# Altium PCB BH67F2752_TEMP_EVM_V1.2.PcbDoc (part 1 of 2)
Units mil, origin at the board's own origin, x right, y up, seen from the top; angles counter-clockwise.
Board outline 4690.02 x 3082.03 mil, 2 copper layers (Top Layer, Bottom Layer); 69 components, 83 nets, 365 pads, 122 vias.
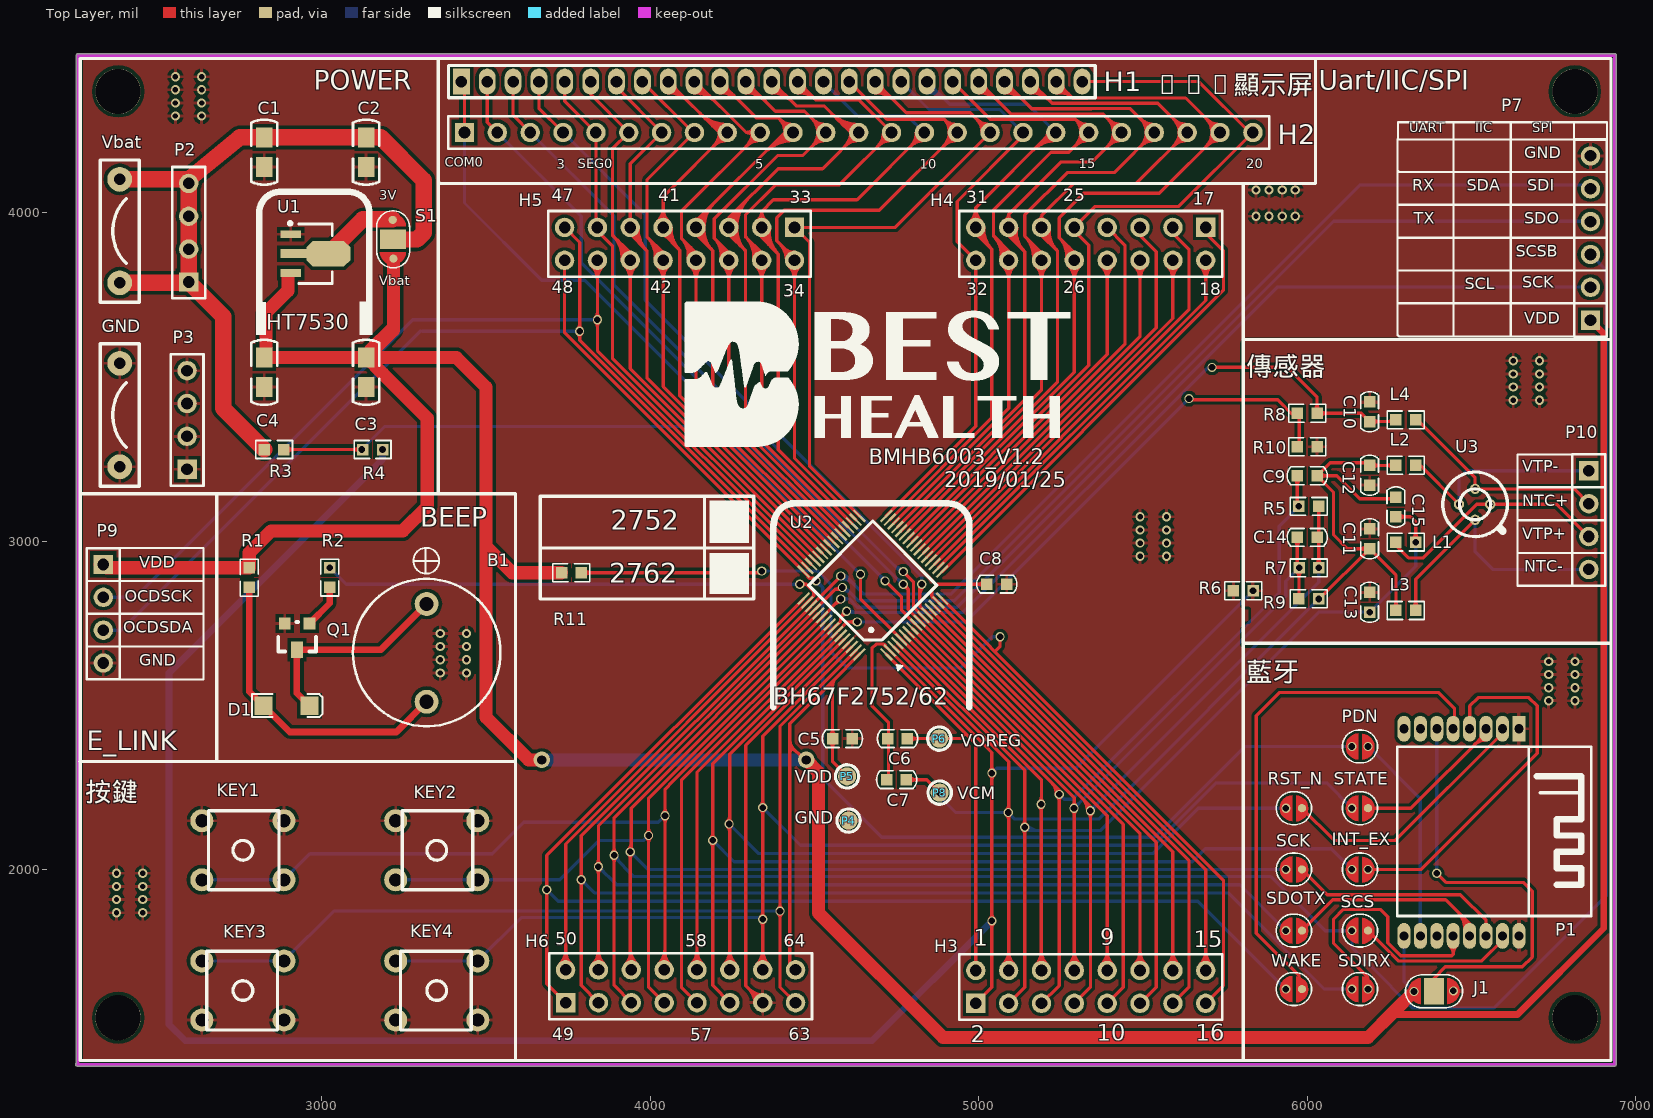
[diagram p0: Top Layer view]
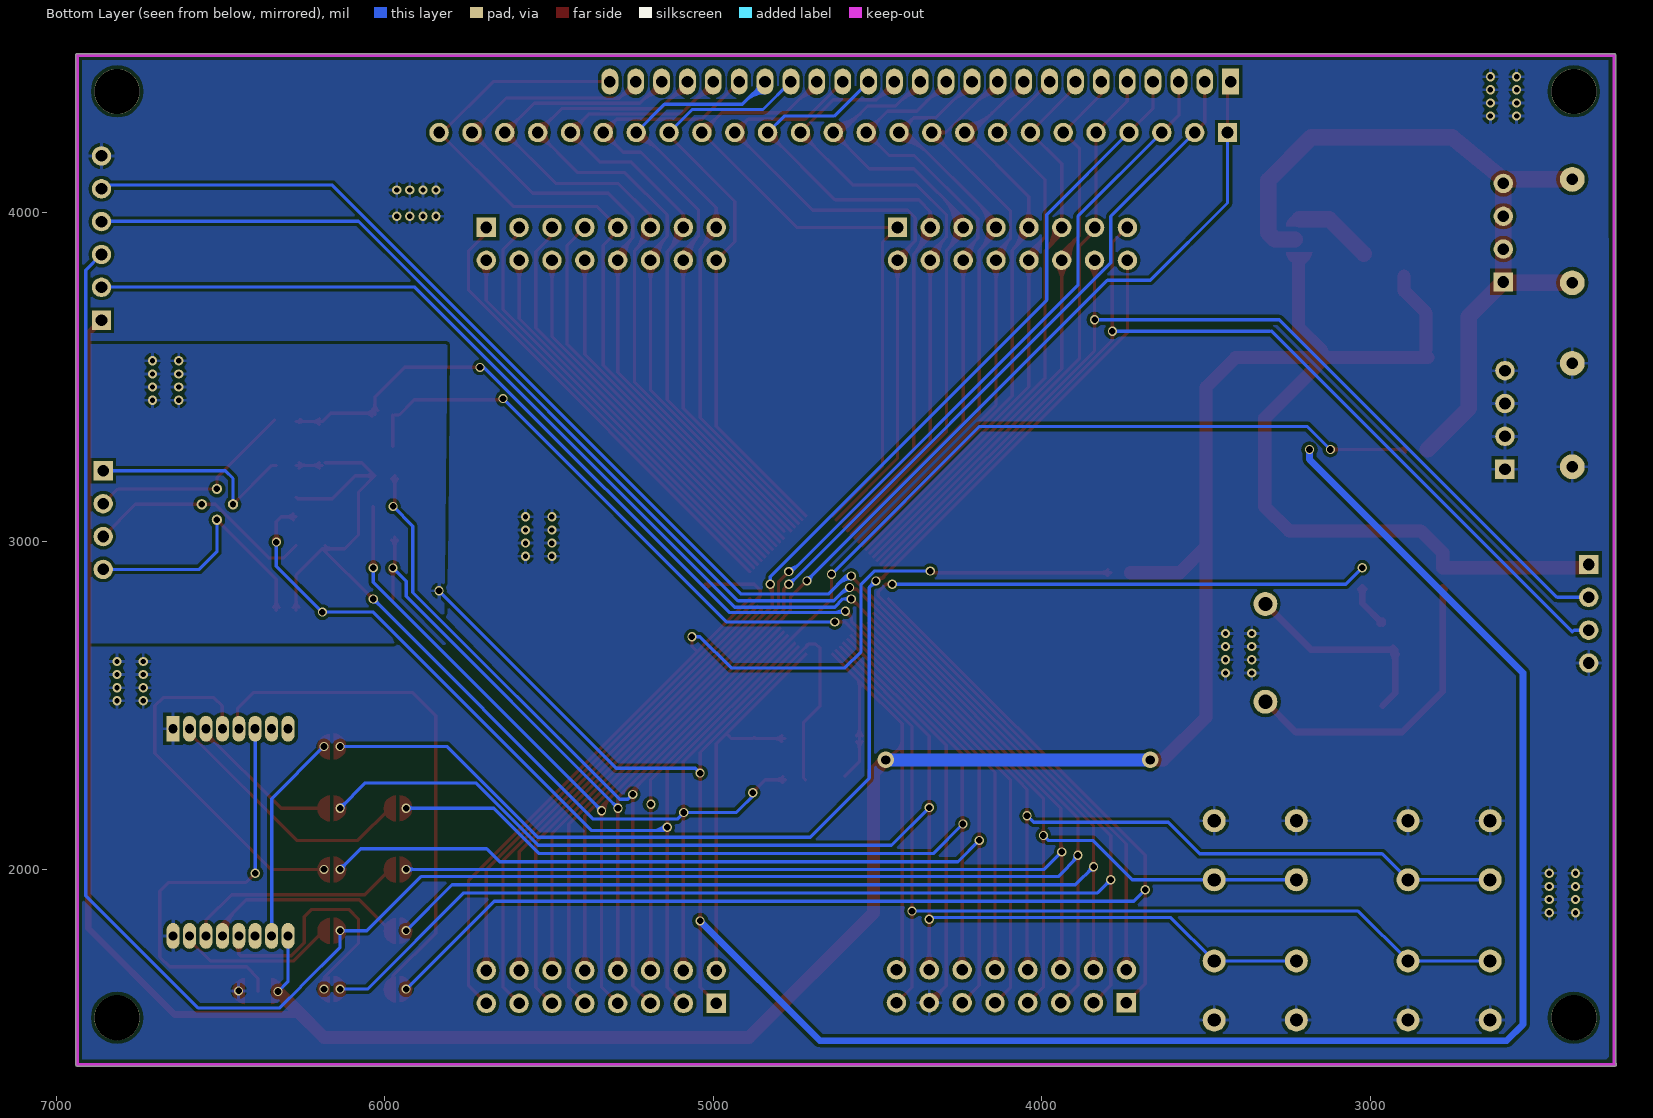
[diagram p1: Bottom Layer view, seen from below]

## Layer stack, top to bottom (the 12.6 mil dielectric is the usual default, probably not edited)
Top Solder: solder mask 0.4, Solder Resist, Dk 3.5
Top Layer: signal copper 1.4
Dielectric1: dielectric 12.6, FR-4, Dk 4.8
Bottom Layer: signal copper 1.4
Bottom Solder: solder mask 0.4, Solder Resist, Dk 3.5

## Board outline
2255.92,1402.93 cw(c2255.92,1407.95) 2252.91,1411.96 2252.91,4479.95 cw(c2257.92,4479.95) 2257.92,4484.97 6935.92,4484.97 cw(c6935.92,4479.95) 6940.94,4479.95 6940.94,1407.95 cw(c6935.92,1407.95) 6935.92,1402.93

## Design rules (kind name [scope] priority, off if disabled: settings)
Clearance Clearance_1 [InPolygon] p1: gap=10
Clearance [All] p2: gap=6
MinimumSolderMaskSliver [All] p1: minsoldermaskwidth=0
NetAntennae [All] p1: netantennaetolerance=1
PolygonConnect [All] p1: connectstyle=Relief reliefconductorwidth=10 reliefentries=4 polygonreliefangle="90 Angle" airgapwidth=10
RoutingVias [All] p1: holewidth=28 width=50 viastyle="Through Hole" minholewidth=10 minwidth=10 maxholewidth=28 maxwidth=50
SilkToSilkClearance [All] p1: silktosilkclearance=0
SilkToSolderMaskClearance [IsPad] p1: minsilkscreentomaskgap=-1 clearancetoexposedcopper=TRUE
SolderMaskExpansion [All] p1: expansion=4
Width [All] p1: maxlimit=50 minlimit=10 preferedwidth=10
26 further rules are at their usual default settings.

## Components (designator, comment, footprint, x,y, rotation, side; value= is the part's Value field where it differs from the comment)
B1 "Beep" BEEP_12MM 3319.29,2810 r270 top
C1 "CAPACITOR" C0805 2825,4140 r90 top
C2 "ECAP" C0805 3135,4230 r270 top
C3 "ECAP" C0805 3135,3560.1 r270 top
C4 "CAPACITOR" C0805 2825,3470 r90 top
C5 "106" CAP_0603 4585,2400 r180 top
C6 "106" CAP_0603 4752.71,2400 r180 top
C7 "105" CAP_0603 4750,2275 r0 top
C8 "104" CAP_0603 5055,2870 r0 top
C9 "104" CAP_0603 6000,3200 r180 top
C10 "104" CAP_0603 6190,3395 r90 top
C11 "104" CAP_0603 6190,3008.24 r90 top
C12 "104" CAP_0603 6190,3201.62 r270 top
C13 "104" CAP_0603 6190,2814.86 r90 top
C14 "104" CAP_0603 6000,3012.73 r180 top
C15 "104" CAP_0603 6270,3105 r270 top
D1 "SS14" DIODE 2962.5,2500 r180 top
GND "CONNET*2" "CLIP POWER PIN" 2385,3385 r90 top (schematic designator GND1)
H1 "HEADER36" "Header25(2mm) - duplicate" 3425,4400 r0 top
H2 "HEADER36" Header252.54mm) 3434.57,4245 r0 top
H3 "HEADER8*2" HEAD2X8 5780,1600 r180 top
H4 "HEADER8*2" 2HEAD2X8 6307,4130 r180 top
H5 "HEADER8*2" 3HEAD2X8 4650.2,3995 r180 top
H6 "HEADER8*2" "4HEAD2X8 - DUPLICATE" 6481.38,1607 r180 top
INT_EX "JUMPER" JUMP_2 6167.05,2000.75 r0 top (schematic designator INT_EX1)
J1 "Header 3" JUMP_3 6435,1550 r180 top
KEY1 "SW-PB" AN66 2760,2060 r90 top
KEY2 "SW-PB" AN66 3350,2060 r90 top
KEY3 "SW-PB" AN66 2760,1633 r270 top
KEY4 "SW-PB" AN66 3350,1633 r270 top
L1 "BEAD" RES_0603 6300,2998.24 r180 top
L2 "BEAD" RES_0603 6300,3231.62 r0 top
L3 "BEAD" RES_0603 6300,2790 r0 top
L4 "BEAD" RES_0603 6300,3370 r0 top
P1 "Header 8X2A" BC7602 6570,2115 r270 top
P2 "Header 4" HDR1X4 2595,3790 r90 top
P3 "Header 4" HDR1X4 2590,3220 r90 top
P4 "PAD" PAD 4485,2200 r0 top
P5 "PAD" PAD 4480.62,2334.49 r0 top
P6 "PAD" PAD 4761.34,2449.49 r0 top
P7 "Header 6H" HEAD1X6 6830,3685 r90 top
P8 "PAD" PAD 4762.48,2285 r0 top
P9 "Header 4" HDR1X4 2335,2930 r270 top
P10 "IRSensor Pin" HDR1X4 6857.36,3215 r270 top
PDN "JUMPER" JUMP_2 6167.05,2374.96 r0 top (schematic designator PDN1)
Q1 "8050" SOT-23 2925,2710 r180 top
R1 "20R" RES_0603 2779.29,2890 r270 top
R2 "1K" RES_0603 3024.29,2890 r90 top
R3 "RES0603" RES_0603 2855,3280 r180 top
R4 "RES0603" RES_0603 3155,3280 r180 top
R5 "RES0603" RES_0603 6004.75,3106.72 r0 top
R6 "RES0603" RES_0603 5805,2850 r0 top
R7 "RES0603" RES_0603 6005.18,2919.45 r180 top
R8 "RES0603" RES_0603 6000,3390 r0 top
R9 "RES0603" RES_0603 6004.75,2825.81 r0 top
R10 "RES0603" RES_0603 6000,3288.54 r180 top
R11 "RES0603" RES_0603 3760,2905 r180 top
RST_N "JUMPER" JUMP_2 5965.97,2187.17 r0 top (schematic designator RST_N1)
S1 "SW-3" JUMP_3 3298.01,3969 r270 top
SCK "JUMPER" JUMP_2 5965.97,2000.75 r0 top (schematic designator SCK1)
SCS "JUMPER" JUMP_2 6167.05,1814.33 r0 top (schematic designator SCS1)
SDIRX "JUMPER" JUMP_2 6167.05,1636.41 r0 top (schematic designator SDIRX1)
SDOTX "JUMPER" JUMP_2 5965.97,1814.33 r0 top (schematic designator SDOTX1)
STATE "JUMPER" JUMP_2 6167.05,2187.17 r0 top (schematic designator STATE1)
U1 "HT7530" SOT89M 2980.63,3876 r0 top
U2 "BH67F2752" 64PIN(LQFP) 4715,2660 r135 top
U3 "IRSensor" TS318_115 6555,3115 r180 top
Vbat "CONNET*2" "CLIP POWER PIN" 2385,3945 r90 top (schematic designator Vbat1)
WAKE "JUMPER" JUMP_2 5965.97,1636.41 r0 top (schematic designator WAKE1)

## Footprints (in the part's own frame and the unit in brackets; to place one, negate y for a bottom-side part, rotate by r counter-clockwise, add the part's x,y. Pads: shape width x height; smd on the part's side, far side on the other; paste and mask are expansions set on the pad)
2HEAD2X8 [mm]
  rect 1.5x1.5 hole 0.9: 1(15.646,4.42)
  round 1.5 hole 0.9: 2(15.646,6.96) 3(18.186,4.42) 4(18.186,6.96) 5(20.726,4.42) 6(20.726,6.96) 7(23.266,4.42) 8(23.266,6.96) 9(25.806,4.42) 10(25.806,6.96) 11(28.346,4.42) 12(28.346,6.96) 13(30.886,4.42) 14(30.886,6.96) 15(33.426,4.42) 16(33.426,6.96)
  silkscreen extent 14.38,3.15 34.7,8.23
3HEAD2X8 [mm]
  rect 1.5x1.5 hole 0.9: 1(5.359,0.991)
  round 1.5 hole 0.9: 2(5.359,3.531) 3(7.899,0.991) 4(7.899,3.531) 5(10.439,0.991) 6(10.439,3.531) 7(12.979,0.991) 8(12.979,3.531) 9(15.519,0.991) 10(15.519,3.531) 11(18.059,0.991) 12(18.059,3.531) 13(20.599,0.991) 14(20.599,3.531) 15(23.139,0.991) 16(23.139,3.531)
  silkscreen extent 4.09,-0.28 24.41,4.8
"4HEAD2X8 - DUPLICATE" [mm]
  rect 1.5x1.5 hole 0.9: 1(69.571,0.279)
  round 1.5 hole 0.9: 2(69.571,-2.261) 3(67.031,0.279) 4(67.031,-2.261) 5(64.491,0.279) 6(64.491,-2.261) 7(61.951,0.279) 8(61.951,-2.261) 9(59.411,0.279) 10(59.411,-2.261) 11(56.871,0.279) 12(56.871,-2.261) 13(54.331,0.279) 14(54.331,-2.261) 15(51.791,0.279) 16(51.791,-2.261)
  silkscreen extent 50.52,-3.53 70.84,1.55
64PIN(LQFP) [mil]
  rect 50x7 smd: 1(-5,0) 2(-5,-16) 3(-5,-32) 4(-5,-48) 5(-5,-64) 6(-5,-80) 7(-5,-96) 8(-5,-112) 9(-5,-128) 10(-5,-144) 11(-5,-160) 12(-5,-176) 13(-5,-192) 14(-5,-208) 15(-5,-224) 16(-5,-240) 33(351,-240) 34(351,-224) 35(351,-208) 36(351,-192) 37(351,-176) 38(351,-160) 39(351,-144) 40(351,-128) 41(351,-112) 42(351,-96) 43(351,-80) 44(351,-64) 45(351,-48) 46(351,-32) 47(351,-16) 48(351,0)
  rect 7x50 smd: 17(53,-298) 18(69,-298) 19(85,-298) 20(101,-298) 21(117,-298) 22(133,-298) 23(149,-298) 24(165,-298) 25(181,-298) 26(197,-298) 27(213,-298) 28(229,-298) 29(245,-298) 30(261,-298) 31(277,-298) 32(293,-298) 49(293,58) 50(277,58) 51(261,58) 52(245,58) 53(229,58) 54(213,58) 55(197,58) 56(181,58) 57(165,58) 58(149,58) 59(133,58) 60(117,58) 61(101,58) 62(85,58) 63(69,58) 64(53,58)
  silkscreen extent -65,-258 311,18
AN66 [mil] "DIP PUSH BOTTON (6MM*6MM)"
  round 70 hole 40: 1(-90,125) 1(-90,-125) 2(90,125) 2(90,-125)
  silkscreen extent -120,-110 120,105
BC7602 [mm]
  rect 2x1 hole 0.7: 1(-8,1.89)
  oval 2x1 hole 0.7: 2(-8,0.62) 3(-8,-0.65) 4(-8,-1.92) 5(-8,-3.19) 6(-8,-4.46) 7(-8,-5.73) 8(-8,-7) 9(8.016,-7) 10(8.016,-5.73) 11(8.016,-4.46) 12(8.016,-3.19) 13(8.016,-1.92) 14(8.016,-0.65) 15(8.016,0.62) 16(8.016,1.89)
  silkscreen extent -6.6,-7.51 6.48,7.48
BEEP_12MM [mm]
  round 1.85 hole 1.1: 1(0,0) 2(7.569,0)
  silkscreen extent -4.34,-5.7 9.46,5.7
C0805 [mil] "0805 CAPCITOR"
  rect 60x50 smd: 1(0,0) 2(90,0)
  silkscreen extent -54,-40 144,40, body extent 6,-25 84,24, height 31
CAP_0603 [mil]
  rect 35x35 smd: 1(-30,0) 2(30,0)
  silkscreen extent -61,-27 61,27
"CLIP POWER PIN" [mm] "USE PAPER CLIP AS POWER PIN(PITCH=8MM)"
  round 1.924 hole 0.9: 1(-4,0) 2(4,0)
  silkscreen extent -5.5,-1.5 5.5,1.5
DIODE [mm]
  rect 1.4x1.4 smd: 1(0,0) 2(3.556,0)
  silkscreen extent -1.02,-0.89 4.44,0.89
HDR1X4 [mm] "Connector; Header; 4 Position"
  rect 1.5x1.5 hole 0.9: 1(0,0)
  round 1.5 hole 0.9: 2(2.54,0) 3(5.08,0) 4(7.62,0)
  silkscreen extent -1.27,-1.27 8.89,1.27
HEAD1X6 [mm]
  rect 1.5x1.5 hole 0.9: 1(-0.287,-0.822)
  round 1.5 hole 0.9: 2(2.253,-0.822) 3(4.793,-0.822) 4(7.333,-0.822) 5(9.873,-0.822) 6(12.413,-0.822)
  silkscreen extent -1.56,-2.09 13.68,0.45
HEAD2X8 [mm]
  round 1.5 hole 0.9: 1(20.041,-2.388) 3(17.501,-2.388) 4(17.501,0.152) 5(14.961,-2.388) 6(14.961,0.152) 7(12.421,-2.388) 8(12.421,0.152) 9(9.881,-2.388) 10(9.881,0.152) 11(7.341,-2.388) 12(7.341,0.152) 13(4.801,-2.388) 14(4.801,0.152) 15(2.261,-2.388) 16(2.261,0.152)
  rect 1.5x1.5 hole 0.9: 2(20.041,0.152)
  silkscreen extent 0.99,-3.66 21.31,1.42
"Header25(2mm) - duplicate" [mm]
  rect 1.3x2 hole 0.9: 1(0,0)
  oval 1.3x2 hole 0.9: 2(2,0) 3(4,0) 4(6,0) 5(8,0) 6(10,0) 7(12,0) 8(14,0) 9(16,0) 10(18,0) 11(20,0) 12(22,0) 13(24,0) 14(26,0) 15(28,0) 16(30,0) 17(32,0) 18(34,0) 19(36,0) 20(38,0) 21(40,0) 22(42,0) 23(44,0) 24(46,0) 25(48,0)
  silkscreen extent -1,-1.25 49.02,1.25
Header252.54mm) [mm]
  rect 1.5x1.5 hole 0.9: 1(0,0)
  round 1.5 hole 0.9: 2(2.54,0) 3(5.08,0) 4(7.62,0) 5(10.16,0) 6(12.7,0) 7(15.24,0) 8(17.78,0) 9(20.32,0) 10(22.86,0) 11(25.4,0) 12(27.94,0) 13(30.48,0) 14(33.02,0) 15(35.56,0) 16(38.1,0) 17(40.64,0) 18(43.18,0) 19(45.72,0) 20(48.26,0) 21(50.8,0) 22(53.34,0) 23(55.88,0) 24(58.42,0) 25(60.96,0)
  silkscreen extent -1.27,-1.27 62.23,1.27
JUMP_2 [mil]
  round 25 smd: 1(-31,1) 2(18,1)
  oval 95x88 on Top Paste: 2(-6,1)
  oval 95x88 on Top Solder: 2(-6,1)
  Top Layer region: 8.15,38.48 17.76,34.5 26.01,28.17 32.34,19.92 36.32,10.31 37.68,0 36.32,-10.31 32.34,-19.92 26.01,-28.17 17.76,-34.5 8.15,-38.48 0,-39.56 0,39.56
  Top Layer region: -20.31,-37.48 -29.92,-33.5 -38.17,-27.17 -44.5,-18.92 -48.48,-9.31 -49.84,1 -48.48,11.31 -44.5,20.92 -38.17,29.17 -29.92,35.5 -20.31,39.48 -12.16,40.56 -12.16,-38.56
  silkscreen extent -60,-49 47,51
JUMP_3 [mil]
  round 25 smd: 1(-10,-82) 3(108,-80)
  rect 60x80 smd: 2(49,-81)
  oval 162x88 on Top Paste: 2(49,-81)
  oval 162x88 on Top Solder: 2(49,-81)
  Top Layer region: 0.69,-119.98 -8.92,-116 -17.17,-109.67 -23.5,-101.42 -27.48,-91.81 -28.84,-81.5 -27.48,-71.19 -23.5,-61.58 -17.17,-53.33 -8.92,-47 0.69,-43.02 8.84,-41.94 8.84,-121.06
  Top Layer region: 97.15,-43.02 106.76,-47 115.01,-53.33 121.34,-61.58 125.32,-71.19 126.68,-81.5 125.32,-91.81 121.34,-101.42 115.01,-109.67 106.76,-116 97.15,-119.98 89,-121.06 89,-41.94
  silkscreen extent -38,-131 136,-30
PAD [mm]
  round 1.4 smd: 1(3.014,-1.257)
  silkscreen extent 2.12,-2.16 3.91,-0.36
RES_0603 [mil]
  rect 35x35 smd: 1(30,0) 2(-30,0)
  silkscreen extent -56,-27 56,27
SOT89M [mm] "SOT89, 3-Leads, Body 4.5x2.4 mm, Pitch 1.5mm, Lead Span 4.1mm, IPC Low Density"
  rect 1.6x0.6 smd: 1(-1.9,1.5) 3(-1.9,-1.5)
  rect 2x0.7 smd: 2(-1.7,0)
  oct 3.4x2 smd: 2(1,0)
  silkscreen extent -2.07,-2.3 1.3,2.47, body extent -2.39,-2.25 1.91,2.25, height 1.51
SOT-23 [mil]
  rect 36x36 smd: 1(-37.5,-40) 2(37.5,-40)
  rect 36x50 smd: 3(0.5,40)
  silkscreen extent -58,-45 58,45
TS318_115 [mm]
  round 0.8 hole 0.5: 1(-0.051,0.051) 2(1.118,-1.143) 3(2.362,0.051) 4(1.118,1.245)
  silkscreen extent -1.38,-2.45 3.61,2.55

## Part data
C1 C2 C3 C4: "Capacitor"
C5 C6 C7 C8: library part CAP(1)
C9 C10 C11 C12 C13 C14 C15: library part Cap, "Capacitor"
D1: library part DIODE(1)
GND Vbat: "2CONNET*2.54"
INT_EX PDN RST_N SCK SCS SDIRX SDOTX STATE WAKE: library part JUMPER2, "JUMPER FOR BREAK CIRCUTS"
J1: "Header, 3-Pin"
KEY1 KEY2 KEY3 KEY4: "Switch"
L1 L2 L3 L4 R1 R2: library part RES(1)
P1: "Header, 8-Pin, Dual row"
P2 P3 P9: "Header, 4-Pin"
P7: "Header, 6-Pin, Right Angle"
P10: library part "Header 4", "Header, 4-Pin"
Q1: library part NPN(1)
R3 R4 R5 R6 R7 R8 R9 R10 R11: library part Res2, "Resistor"
U1: library part LDO, "Low Drop Regulator"

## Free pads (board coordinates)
  round 137.8 hole 137.8: 5(2380,1550) 5(2380,4370) 5(6815,1550) 5(6815,4370)

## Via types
v1: diameter 28, hole 20, Top Layer to Bottom Layer, tented top, 64 vias
v2: diameter 28, hole 16, Top Layer to Bottom Layer, tented top, 56 vias
v3: diameter 50, hole 28, Top Layer to Bottom Layer, tented top, 2 vias

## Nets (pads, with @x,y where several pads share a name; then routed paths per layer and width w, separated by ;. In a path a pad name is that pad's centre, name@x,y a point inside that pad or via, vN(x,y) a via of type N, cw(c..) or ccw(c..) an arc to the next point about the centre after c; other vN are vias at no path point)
2INT_EXT: INT_EX.2@6185.05,2001.75 P1.4 | length 1164.8
  Top Layer w10: v1(6185.05,2001.75) 6346.75,2001.75 6700,2355 6700,2500 6675,2525 6520,2525 6494.41,2499.41 P1.4@6494.41,2429.96 ; INT_EX.2@6190.35,1996.45 cw(c6203.16,1983.64) 6203.16,2001.75 cw(c6203.16,2019.86) INT_EX.2@6190.35,2007.05 ; INT_EX.2@6191.41,1995.39 cw(c6206.78,1980.02) 6206.78,2001.75 cw(c6206.78,2023.48) INT_EX.2@6191.41,2008.12
2PDN: P1.10 PDN.2@6185.05,2375.96 | length 642.6
  Bottom Layer w10: v1(6185.05,2375.96) 6344.41,2216.6 P1.10@6344.41,1799.41
2RST_N: P1.2 RST_N.2@5983.97,2188.17 | length 828
  Top Layer w10: RST_N.2@5983.97,2180.67 cw(c5983.97,2162.56) 5996.78,2175.37 cw(c6009.58,2188.17) RST_N.2@5991.47,2188.17 ; RST_N.2@5983.97,2188.17 6082.15,2090 6267.53,2090 6594.41,2416.88 P1.2@6594.41,2429.96
2SCK: P1.14 SCK.2@5983.97,2001.75 | length 700.3
  Top Layer w10: SCK.2@5983.97,1994.25 cw(c5983.97,1976.14) 5996.78,1988.95 cw(c6009.58,2001.75) SCK.2@5991.47,2001.75 ; SCK.2@5983.97,2001.75 6060.73,1925 6466,1925 6544.41,1846.59 P1.14@6544.41,1799.41
2SCSB: P1.15 SCS.2@6185.05,1815.33 | length 515.4
  Top Layer w10: SCS.2@6185.05,1807.83 cw(c6185.05,1789.73) 6197.85,1802.53 cw(c6210.66,1815.33) SCS.2@6192.55,1815.33 ; SCS.2@6185.05,1815.33 6277.38,1723 6531.08,1723 6594.41,1786.33 P1.15@6594.41,1799.41
"2SD0 TX": P1.13 SDOTX.2@5983.97,1815.33 | length 743.5
  Top Layer w10: SDOTX.2@5983.97,1815.33 6077.64,1909 6421,1909 6494.41,1835.59 P1.13@6494.41,1799.41 ; SDOTX.2@5983.97,1822.83 ccw(c5983.97,1840.94) 5996.78,1828.14 ccw(c6009.58,1815.33) SDOTX.2@5991.47,1815.33 ; 6457.68,1872.32 cw(c6404.45,1819.09) P1.13@6479.72,1819.09 ; 6474.75,1855.25 cw(c6438.59,1819.09) P1.13@6489.72,1819.09
"2SDI RX": P1.12 SDIRX.2@6185.05,1637.41 | length 914.2
  Top Layer w10: SDIRX.2@6178.68,1643.77 ccw(c6163.32,1659.14) 6185.05,1659.14 ccw(c6206.78,1659.14) SDIRX.2@6191.41,1643.77 ; SDIRX.2@6179.75,1642.71 ccw(c6166.94,1655.52) 6185.05,1655.52 ccw(c6203.16,1655.52) SDIRX.2@6190.35,1642.71 ; v1(6185.05,1637.41) 6185.05,1671.24 6080,1776.29 6080,1850 6110,1880 6222.82,1880 6245,1857.82 6245,1778.01 6284.01,1739 6440,1739 6444.41,1743.41 P1.12@6444.41,1799.41 ; P1.12@6434.03,1769.34 cw(c6408.96,1744.27) 6444.41,1744.27 cw(c6479.86,1744.27) P1.12@6454.79,1769.34
2SPI-UP_N: J1.2@6386,1631 P1.6 | length 1318.8
  Top Layer w10: J1.2@6386,1631 6386,1671 6420,1705 6655,1705 6685,1735 6685,1935 6657.8,1962.2 6422.21,1962.2 v1(6394.41,1990)
  Bottom Layer w10: v1(6394.41,1990) P1.6@6394.41,2429.96
2STATE: P1.3 STATE.2@6185.05,2188.17 | length 572.7
  Top Layer w10: STATE.2@6185.05,2188.17 6315.7,2188.17 6544.41,2416.88 P1.3@6544.41,2429.96 ; STATE.2@6190.35,2182.87 cw(c6203.16,2170.06) 6203.16,2188.17 cw(c6203.16,2206.28) STATE.2@6190.35,2193.47 ; 6508.07,2380.54 cw(c6544.41,2344.19) P1.3@6544.41,2395.59 ; 6524.01,2396.48 ccw(c6510.22,2410.28) P1.3@6529.72,2410.28 ; 6525.14,2397.61 cw(c6544.41,2378.33) P1.3@6544.41,2405.59
2WAKEUP: P1.5 WAKE.2@5983.97,1637.41 | length 1679.6
  Top Layer w10: 5975,1653.04 ccw(c5999.61,1653.04) WAKE.2@5982.21,1635.64 ; 5975,1677.18 ccw(c6023.75,1677.18) WAKE.2@5989.28,1642.71 ; WAKE.2@5976.77,1639.5 ccw(c5970.06,1641.44) 5975,1646.39 ; WAKE.2@5981.89,1644.61 cw(c5979.94,1651.33) 5975,1646.39 ; WAKE.2@5983.97,1637.41 5975,1646.39 ; P1.5@6440.78,2429.96 6448.05,2437.22 6448.05,2491.95 6400,2540 5915,2540 5845,2470 5845,1807.78 5975,1677.78 5975,1646.39
AN0: C13.1 C15.2 H3.4 L1.2 U2.4 | length 3268.3
  Top Layer w10: U2.4@4752.48,2690.41 5140,2302.88 v1(5140,2130) 5140,1643 H3.4@5091,1594 ; v1@5133.64,2123.64 cw(c5118.27,2108.27) 5140,2108.27 cw(c5161.73,2108.27) v1@5146.36,2123.64 ; v1@5133.64,2136.36 ccw(c5118.27,2151.73) 5140,2151.73 ccw(c5161.73,2151.73) v1@5146.36,2136.36 ; C13.1@6190,2784.86 C13.1@6190.07,2784.93 ; C15.2@6270,3075 6315,3075 6330,3060 v1(6330,2998.24) L1.2@6330,2988.24 ; C15.2@6278.84,3066.16 cw(c6300.18,3044.82) 6300.18,3075 cw(c6300.18,3105.18) C15.2@6278.84,3083.84 ; L1.2@6321.16,3007.08 ccw(c6299.82,3028.42) 6330,3028.42 ccw(c6360.18,3028.42) L1.2@6338.84,3007.08 ; L1.2@6323.64,3004.6 ccw(c6308.27,3019.97) 6330,3019.97 ccw(c6351.73,3019.97) L1.2@6336.36,3004.6 ; C13.1@6190.07,2784.93 6190.14,2785 v1(6190,2785) C13.1@6190.07,2784.93
  Bottom Layer w10: v1@5139.29,2129.29 ccw(c5161.73,2151.73) 5161.73,2120 ; v1@5146.36,2136.36 ccw(c5185.87,2175.87) 5185.87,2120 ; 5150,2120 5370,2120 6035,2785 v1(6190,2785) 6330,2925 v1(6330,2998.24)
AN1: H3.5 R3.2 R4.1 U2.5 | length 3753.9
  Top Layer w10: R3.2@2885,3280 v1(3121.4,3280) R4.1@3125,3280 ; R3.2@2893.84,3271.16 cw(c2915.18,3249.82) 2915.18,3280 cw(c2915.18,3310.18) R3.2@2893.84,3288.84 ; R4.1@3115.03,3273.64 ccw(c3099.67,3258.27) 3099.67,3280 ccw(c3099.67,3301.73) R4.1@3115.03,3286.36 ; R4.1@3116.16,3271.16 ccw(c3094.82,3249.82) 3094.82,3280 ccw(c3094.82,3310.18) R4.1@3116.16,3288.84 ; v1(4640,2900) 4640,2825.51 U2.5@4763.79,2701.72 5191,2274.51 v1@5191,2200 ; H3.5@5173.66,1711.34 ccw(c5134.2,1750.8) 5190,1750.8 ; H3.5@5180.73,1704.27 ccw(c5158.34,1726.66) 5190,1726.66 ; v1@5183.64,2193.64 cw(c5168.27,2178.27) 5190,2178.27 cw(c5211.73,2178.27) v1@5196.36,2193.64 ; v1@5183.64,2206.36 ccw(c5165.86,2224.14) 5191,2224.14 ; 5190,1731.49 ccw(c5228.49,1731.49) H3.5@5201.27,1704.27 ; 5190,1755.63 ccw(c5252.63,1755.63) H3.5@5208.34,1711.34 ; v1(5190,2200) 5190,1695 H3.5@5191,1694 ; 5191,2219.31 ccw(c5209.31,2219.31) v1@5196.36,2206.36
  Bottom Layer w10: v1(3121.4,3280) 3191.4,3350 4190,3350 v1(4640,2900)
AN2: C9.2 H3.6 R5.2 U2.6 | length 2808.3
  Top Layer w10: U2.6@4775.1,2713.03 5245,2243.14 v1(5245,2230) 5245,1648 H3.6@5191,1594 ; 5220.35,2267.79 cw(c5182.56,2230) v1@5236,2230 ; 5237.42,2250.72 cw(c5216.7,2230) v1@5246,2230 ; v1@5238.64,2223.64 cw(c5223.27,2208.27) 5245,2208.27 cw(c5266.73,2208.27) v1@5251.36,2223.64 ; C9.2@5961.16,3191.16 cw(c5939.82,3169.82) 5970,3169.82 cw(c6000.18,3169.82) C9.2@5978.84,3191.16 ; v1(5974.75,3106.72) 5970,3111.47 C9.2@5970,3200 C9.2@5974.75,3195.25
  Bottom Layer w10: v1(5245,2230) 5260,2215 5285.3,2215 5915,2844.7 5915,3046.97 v1(5974.75,3106.72)
AN3: C14.2 H3.7 R7.1 R9.2 U2.7 | length 2823
  Top Layer w10: U2.7@4786.42,2724.35 5291,2219.76 H3.7@5291,1694 ; H3.7@5273.66,1711.34 ccw(c5231.79,1753.21) 5291,1753.21 ccw(c5350.21,1753.21) H3.7@5308.34,1711.34 ; H3.7@5280.73,1704.27 ccw(c5255.93,1729.07) 5291,1729.07 ccw(c5326.07,1729.07) H3.7@5301.27,1704.27 ; v1@5283.64,2181.81 cw(c5265.86,2164.03) 5291,2164.03 ; v1@5283.64,2194.53 ccw(c5265.86,2212.31) 5291,2212.31 ; 5291,2168.86 cw(c5309.31,2168.86) v1@5296.36,2181.81 ; 5291,2207.48 ccw(c5309.31,2207.48) v1@5296.36,2194.53 ; C14.2@5961.16,3003.89 cw(c5939.82,2982.55) 5970,2982.55 cw(c6000.18,2982.55) C14.2@5978.84,3003.89 ; R7.1@5966.35,2910.61 cw(c5945.01,2889.27) 5975.18,2889.27 cw(c6005.36,2889.27) R7.1@5984.02,2910.61 ; R7.1@5968.82,2913.08 cw(c5953.46,2897.72) 5975.18,2897.72 cw(c5996.91,2897.72) R7.1@5981.55,2913.08 ; C14.2@5970,3012.73 5970,2924.63 v1(5975.18,2919.45) 5975.18,2826.25 R9.2@5974.75,2825.81
  Bottom Layer w10: v1(5290,2188.17) 5934.97,2833.15 5934.97,2879.42 v1@5975,2919.45 ; v1@5290,2197.17 ccw(c5290,2218.9) 5305.36,2203.53 ccw(c5320.73,2188.17) v1@5299,2188.17
AN4: H6.10 R8.2 R10.1 U2.58 | length 3192.2
  Top Layer w10: H6.10@4125.03,1713.34 ccw(c4083.16,1755.21) 4142.38,1755.21 ccw(c4201.59,1755.21) H6.10@4159.72,1713.34 ; H6.10@4132.1,1706.27 ccw(c4107.3,1731.07) 4142.38,1731.07 ccw(c4177.45,1731.07) H6.10@4152.65,1706.27 ; H6.10@4142.38,1696 4142.38,2298.09 U2.58@4568.63,2724.35 ; U2.58@4573.32,2729.03 4599.28,2755 v1(4630,2755) ; v1@4623.64,2748.64 ccw(c4608.27,2733.27) 4608.27,2755 ccw(c4608.27,2776.73) v1@4623.64,2761.36 ; v1@5643.52,3431.48 5910,3431.48 5956.48,3385 R8.2@5970,3385 ; R10.1@5975.37,3288.91 R8.2@5975.37,3384.63
  Bottom Layer w10: H6.10@4139.2,1699.17 H6.10@4142.38,1696 ; v1(4630,2755) 4960,2755 v1(5640,3435)
AN5: C10.1 H6.9 L4.2 R8.1 U2.57 | length 3745.9
  Top Layer w10: H6.9@4142.38,1596 4095,1643.37 4095,2273.34 U2.57@4557.32,2735.66 4579.38,2757.72 4579.38,2769.6 v1(4597.62,2787.85) ; v1@4588.62,2787.85 cw(c4566.9,2787.85) 4582.26,2772.49 cw(c4597.62,2757.12) v1@4597.62,2778.85 ; v1(5710,3530) 5939.75,3530 6030,3439.75 R8.1@6030,3390 R8.1@6030,3385 ; R8.1@6021.16,3398.84 ccw(c5999.82,3420.18) 6030,3420.18 ccw(c6060.18,3420.18) 6038.84,3398.84 ccw(c6060.18,3420.18) 6060.18,3390 ccw(c6060.18,3359.82) R8.1@6038.84,3381.16 ; R8.1@6035,3390 6165,3390 C10.1@6190,3365 6247.5,3365 ; C10.1@6198.84,3356.16 cw(c6220.18,3334.82) 6220.18,3365 cw(c6220.18,3395.18) C10.1@6198.84,3373.84 ; L4.2@6270,3365 6247.5,3365 ; 6247.5,3365 ccw(c6247.5,3375.71) 6257.88,3373.08 cw(c6247.5,3375.71) 6247.5,3365 ; 6251.89,3365 cw(c6251.89,3351.89) 6261.16,3361.16 ccw(c6251.89,3351.89) 6251.89,3365
  Bottom Layer w10: v1(4597.62,2787.85) 4601.48,2784 4951.57,2784 v1@5701.46,3533.89 ; v1@4603.99,2794.21 ccw(c4628.65,2818.87) 4628.65,2784
AN6: H6.8 KEY1.1 U2.56 | length 2946.2
  Top Layer w10: H6.8@4025.03,1713.34 ccw(c3976.83,1761.55) 4045,1761.55 ; H6.8@4032.1,1706.27 ccw(c4000.97,1737.4) 4045,1737.4 ; v1@4038.64,2158.64 cw(c4023.27,2143.27) 4045,2143.27 cw(c4066.73,2143.27) v1@4051.36,2158.64 ; v1@4038.64,2171.36 ccw(c4023.27,2186.73) 4045,2186.73 ccw(c4066.73,2186.73) v1@4051.36,2171.36 ; H6.8@4042.38,1696 4045,1698.62 v1(4045,2165) 4045,2245.97 4069.03,2270 U2.56@4546,2746.97 ; 4045,1748.88 ccw(c4095.26,1748.88) H6.8@4059.72,1713.34
  Bottom Layer w10: KEY1.1@2635,1970 KEY1.1@2885,1970 2964,2049 3519,2049 3615,2145 4025,2145 v1(4045,2165)
AN7: H6.7 KEY2.1 U2.55 | length 2290.5
  Top Layer w10: v1@3988.64,2098.64 cw(c3973.27,2083.27) 3995,2083.27 cw(c4016.73,2083.27) v1@4001.36,2098.64 ; v1@3988.64,2111.36 ccw(c3973.27,2126.73) 3995,2126.73 ccw(c4016.73,2126.73) v1@4001.36,2111.36 ; H6.7@4042.38,1596 3995,1643.37 v1(3995,2105) 3995,2218.6 U2.55@4528.2,2751.8
  Bottom Layer w10: KEY2.1@3225,1970 KEY2.1@3475,1970 3725,1970 3845,2090 3980,2090 v1(3995,2105)
AVSS: C6.2 C7.1 C10.2 C11.2 C12.2 C13.2 H3.2 R4.2 R6.1 R10.2 U2.2 | length 7586
  Top Layer w10: 4707.08,2687.62 cw(c4707.08,2675.41) U2.2@4715.71,2684.04 ; C7.1@4720,2275 4725,2280 4725,2450 4675,2500 4675,2675 4687.62,2687.62 4710.01,2687.62 U2.2@4729.85,2667.78 5022.63,2375 ; H3.2@4991,1594 5040,1643 v1(5040,1845) v1(5040,2295) 5040,2357.63 5022.63,2375 ; 5026.31,2371.31 5022.63,2375 ; v1@5033.64,1838.64 cw(c5018.27,1823.27) 5040,1823.27 cw(c5061.73,1823.27) v1@5046.36,1838.64 ; v1@5033.64,1851.36 ccw(c5018.27,1866.73) 5040,1866.73 ccw(c5061.73,1866.73) v1@5046.36,1851.36 ; v1@5033.64,2288.64 cw(c5018.27,2273.27) 5040,2273.27 cw(c5061.73,2273.27) v1@5046.36,2288.64 ; v1@5033.64,2301.36 ccw(c5018.27,2316.73) 5040,2316.73 ccw(c5061.73,2316.73) v1@5046.36,2301.36
  Bottom Layer w10: v1(5040,2295) 5055,2310 5295,2310 v1(5835,2850)
  Bottom Layer w20: v1(3185,3280) 3185,3250 2535,2600 2535,1530 2585,1480 4675,1480 v1(5040,1845)
  other v2: 6627.42,3430.1 6707.42,3430.1 6627.42,3470.1 6707.42,3470.1 6627.42,3510.1 6707.42,3510.1 6627.42,3550.1 6707.42,3550.1
BEEP: H6.2 R2.1 U2.50 | length 3146
  Top Layer w10: H6.2@3725.03,1713.34 ccw(c3683.16,1755.21) 3742.38,1755.21 ccw(c3801.59,1755.21) H6.2@3759.72,1713.34 ; H6.2@3732.1,1706.27 ccw(c3707.3,1731.07) 3742.38,1731.07 ccw(c3777.45,1731.07) H6.2@3752.65,1706.27 ; H6.2@3742.38,1696 3742.38,2079.11 U2.50@4478.12,2814.86 4497.96,2834.7 4497.96,2847.04 4475,2870 ; v1(4455,2870) 4475,2870 ; v1@4461.74,2864.03 cw(c4475,2852.28) 4475,2870 ; v1@4461.74,2875.97 ccw(c4475,2887.72) 4475,2870
  Bottom Layer w10: v1(3024.29,2920) 3074.29,2870 v1(4455,2870)
COM0: H1.1 H2.1 H3.9 U2.9 | length 3778.7
  Top Layer w10: H1.1@3425,4400 3434.57,4390.43 H2.1@3434.57,4245 ; v1(4715,2880) 4765,2830 4765,2791.02 4804.36,2751.66 U2.9@4809.05,2746.97 5391,2165.02 H3.9@5391,1694 ; H3.9@5373.66,1711.34 ccw(c5331.79,1753.21) 5391,1753.21 ccw(c5450.21,1753.21) H3.9@5408.34,1711.34 ; H3.9@5380.73,1704.27 ccw(c5355.93,1729.07) 5391,1729.07 ccw(c5426.07,1729.07) H3.9@5401.27,1704.27
  Bottom Layer w10: H2.1@3434.57,4245 3434.57,4030.43 3670,3795 3800,3795 v1(4715,2880) ; v1@4706,2880 ccw(c4684.27,2880) 4699.64,2895.36 ccw(c4715,2910.73) v1@4715,2889
COM1: H1.2 H2.2 H3.10 U2.10 | length 3697.8
  Top Layer w10: H1.2@3503.74,4400 3503.74,4275.83 H2.2@3534.57,4245 ; v1@4770,2861 cw(c4770,2839.27) 4785.36,2854.64 cw(c4800.73,2870) v1@4779,2870 ; v1(4770,2870) 4785.67,2854.33 4785.67,2792.97 U2.10@4820.36,2758.29 5440,2138.65 5440,1643 H3.10@5391,1594
  Bottom Layer w10: H2.2@3534.57,4245 3790,3989.57 3790,3847.88 4767.88,2870 v1(4770,2870) ; 4751.02,2886.86 ccw(c4770,2905.84) v1@4770,2879 ; 4756.13,2881.75 cw(c4744.38,2870) v1@4761,2870
COM2: H1.3 H2.3 H3.11 U2.11 | length 3682
  Top Layer w10: H1.3@3582.48,4400 3582.48,4297.09 H2.3@3634.57,4245 ; v1(4770,2908.19) 4801.67,2876.52 4801.67,2799.6 U2.11@4831.67,2769.6 5491,2110.27 H3.11@5491,1694 ; H3.11@5473.66,1711.34 ccw(c5431.79,1753.21) 5491,1753.21 ccw(c5550.21,1753.21) H3.11@5508.34,1711.34 ; H3.11@5480.73,1704.27 ccw(c5455.93,1729.07) 5491,1729.07 ccw(c5526.07,1729.07) H3.11@5501.27,1704.27
  Bottom Layer w10: H2.3@3634.57,4245 3890,3989.57 3890,3780 4761.81,2908.19 v1(4770,2908.19) ; 4740.65,2929.35 ccw(c4770,2958.71) v1@4770,2917.19
COM3: H1.4 H2.4 H3.12 U2.12 | length 3658.8
  Top Layer w10: H1.4@3661.22,4400 3661.22,4318.35 H2.4@3734.57,4245 ; 4820.36,2833.03 cw(c4863.64,2833.03) v1@4833.04,2863.64 ; 4820.36,2857.17 cw(c4839.5,2857.17) v1@4825.97,2870.71 ; v1(4826.67,2870) 4820.36,2863.69 4820.36,2803.54 U2.12@4842.99,2780.92 5540,2083.9 5540,1643 H3.12@5491,1594
  Bottom Layer w10: H2.4@3734.57,4245 3985,3994.57 3985,3735 4826.67,2893.33 v1(4826.67,2870)
GND: C1.1 C2.2 C3.2 C4.1 C5.1 C8.2 GND.1 GND.2 H6.13 J1.1 KEY1.2 KEY2.2 KEY3.2 KEY4.2 P1.1 P1.16 P3.1 P3.2 P3.3 P3.4 P4.1 P7.6 P9.4 Q1.2 R6.2 U1.1 U2.61 | length 1395.2
  Top Layer w10: H6.13@4317.85,1596 ccw(c4258.63,1596) 4300.5,1637.87 ccw(c4342.38,1679.74) H6.13@4342.38,1620.52 ; H6.13@4327.85,1596 ccw(c4292.78,1596) 4317.58,1620.8 ccw(c4342.38,1645.6) H6.13@4342.38,1610.52 ; H6.13@4342.38,1596 4291.14,1647.23 4291.14,2378.98 U2.61@4602.57,2690.41
  Top Layer w40: GND.1@2385,3227.52 GND.1@2385,3230
  other v1: 6445,1632
  other v2: 2375,1870 2455,1870 2375,1910 2455,1910 2375,1950 2455,1950 2375,1990 2455,1990 6735,2515 6815,2515 6735,2555 6815,2555 6735,2595 6815,2595 3360.7,2600 3440.7,2600 6735,2635 6815,2635 3360.7,2640 3440.7,2640 3360.7,2680 3440.7,2680 3360.7,2720 3440.7,2720 5491.34,2955 5571.34,2955 5491.34,2995 5571.34,2995 5491.34,3035 5571.34,3035 5491.34,3075 5571.34,3075 5843.7,3990 5883.7,3990 5923.7,3990 5963.7,3990 5843.7,4070 5883.7,4070 5923.7,4070 5963.7,4070 2554.37,4295 2634.37,4295 2554.37,4335 2634.37,4335 2554.37,4375 2634.37,4375 2554.37,4415 2634.37,4415
INT_EXT: H6.11 INT_EX.1 U2.59 | length 3418.4
  Top Layer w10: v1@4183.64,2083.64 cw(c4168.27,2068.27) 4190,2068.27 cw(c4211.73,2068.27) v1@4196.36,2083.64 ; v1@4183.64,2096.36 ccw(c4168.27,2111.73) 4190,2111.73 ccw(c4211.73,2111.73) v1@4196.36,2096.36 ; H6.11@4242.38,1596 4190,1648.37 v1(4190,2090) 4190,2323.09 U2.59@4579.94,2713.03
  Bottom Layer w10: v1(4190,2090) 4255,2025 5650,2025 5690,2065 6072.8,2065 v1(6136.05,2001.75) ; v1@6127.05,2001.75 ccw(c6105.32,2001.75) 6120.68,2017.12 ccw(c6136.05,2032.48) v1@6136.05,2010.75
KEY3: H6.15 KEY3.1 U2.63 | length 3078
  Top Layer w10: v1@4388.64,1868.64 cw(c4373.27,1853.27) 4395,1853.27 cw(c4416.73,1853.27) v1@4401.36,1868.64 ; v1@4388.64,1881.36 ccw(c4373.27,1896.73) 4395,1896.73 ccw(c4416.73,1896.73) v1@4401.36,1881.36 ; H6.15@4442.38,1596 4395,1643.37 v1(4395,1875) 4395,2437.58 U2.63@4625.2,2667.78
  Bottom Layer w10: KEY3.1@2635,1723 KEY3.1@2885,1723 3037,1875 v1(4395,1875)
KEY4: H6.14 KEY4.1 STATE.1 U2.62 | length 4533.7
  Top Layer w10: H6.14@4325.03,1713.34 ccw(c4283.16,1755.21) 4342.38,1755.21 ccw(c4401.59,1755.21) H6.14@4359.72,1713.34 ; H6.14@4332.1,1706.27 ccw(c4307.3,1731.07) 4342.38,1731.07 ccw(c4377.45,1731.07) H6.14@4352.65,1706.27 ; v1@4336.01,1843.64 cw(c4320.65,1828.27) 4342.38,1828.27 cw(c4364.1,1828.27) v1@4348.74,1843.64 ; v1@4336.01,1856.36 ccw(c4320.65,1871.73) 4342.38,1871.73 ccw(c4364.1,1871.73) v1@4348.74,1856.36 ; v1@4336.01,2183.64 cw(c4320.65,2168.27) 4342.38,2168.27 cw(c4364.1,2168.27) v1@4348.74,2183.64 ; v1@4336.01,2196.36 ccw(c4320.65,2211.73) 4342.38,2211.73 ccw(c4364.1,2211.73) v1@4348.74,2196.36 ; H6.14@4342.38,1696 4342.38,1815.33 ; 4342.38,1818.51 v1(4342.38,1850) ; v1@4342.38,1860 v1(4342.38,2190) 4342.38,2407.58 U2.62@4613.88,2679.09
  Bottom Layer w10: KEY4.1@3225,1723 KEY4.1@3475,1723 3607,1855 4345,1855 4342.38,1852.38 v1(4342.38,1850) ; v1(4342.38,2190) 4457.38,2075 5532.63,2075 5722.63,2265 6059.22,2265 v1(6136.05,2188.17) ; v1@6127.05,2188.17 ccw(c6105.32,2188.17) 6120.68,2203.53 ccw(c6136.05,2218.9) v1@6136.05,2197.17
LNOPO: C14.1 H3.8 R5.1 R7.2 U2.8 | length 2817.2
  Top Layer w10: U2.8@4797.73,2735.66 5340,2193.39 v1(5340,2180) 5340,1643 H3.8@5291,1594 ; 5315.17,2218.23 cw(c5276.94,2180) v1@5331,2180 ; 5332.24,2201.15 cw(c5311.08,2180) v1@5341,2180 ; v1@5333.64,2173.64 cw(c5318.27,2158.27) 5340,2158.27 cw(c5361.73,2158.27) v1@5346.36,2173.64 ; R7.2@6026.35,2928.29 ccw(c6005.01,2949.63) 6035.18,2949.63 ccw(c6065.36,2949.63) R7.2@6044.02,2928.29 ; R7.2@6028.82,2925.81 ccw(c6013.46,2941.18) 6035.18,2941.18 ccw(c6056.91,2941.18) R7.2@6041.55,2925.81 ; R5.1@6034.75,3106.72 6035.18,3106.28 v1(6035.18,2919.45)
  Bottom Layer w10: v1(5340,2180) 6035.18,2875.18 v1(6035.18,2919.45) ; v1@5340,2189 ccw(c5340,2210.73) 5355.36,2195.36 ccw(c5370.73,2180) v1@5349,2180
NetB1_1: B1.1 D1.1 Q1.3 | length 699.2
  Top Layer w20: Q1.3@2918.84,2657.34 cw(c2905.19,2643.69) 2924.5,2643.69 cw(c2943.81,2643.69) Q1.3@2930.16,2657.34 ; Q1.3@2930.16,2664.34 cw(c2943.81,2650.69) 2943.81,2670 cw(c2943.81,2689.31) Q1.3@2930.16,2675.66 ; D1.1@2962.5,2500 2924.5,2538 Q1.3@2924.5,2670 3179.29,2670 B1.1@3319.29,2810
NetB1_2: B1.2 D1.2 R1.1 | length 974.4
  Top Layer w20: R1.1@2773.98,2854.7 cw(c2761.18,2841.89) 2779.29,2841.89 cw(c2797.39,2841.89) R1.1@2784.59,2854.7 ; R1.1@2779.29,2860 2779.29,2543.21 D1.2@2822.5,2500 2902.5,2420 3227.29,2420 B1.2@3319.29,2512
NetQ1_1: Q1.1 R2.2 | length 194.4
  Top Layer w20: Q1.1@2962.5,2750 3024.29,2811.79 R2.2@3024.29,2860 ; Q1.1@2962.5,2758 ccw(c2962.5,2777.31) 2976.16,2763.66 ccw(c2989.81,2750) Q1.1@2970.5,2750 ; R2.2@3018.98,2854.7 cw(c3006.18,2841.89) 3024.29,2841.89 cw(c3042.39,2841.89) R2.2@3029.59,2854.7
NetS1_1: S1.1 U1.2 | length 239.5
  Top Layer w50: U1.2@3020,3876 3125,3981 S1.1@3216.01,3981
NTC+: L4.1 P10.2 U3.2 | length 647.9
  Top Layer w10: L4.1@6335,3370 6511,3194 U3.2@6511,3160 6812.36,3160 P10.2@6857.36,3115
NTC-: L3.1 P10.4 U3.4 | length 864.1
  Top Layer w10: L3.1@6321.16,2798.84 ccw(c6299.82,2820.18) 6330,2820.18 ccw(c6360.18,2820.18) L3.1@6338.84,2798.84 ; L3.1@6330,2790 6330,2885 U3.4@6511,3066
  Bottom Layer w10: U3.4@6511,3066 6511,2969 6565,2915 P10.4@6857.36,2915
OCDSCK: H5.14 P9.2 U2.46 | length 3270.9
  Top Layer w10: H5.14@3821.85,3838.66 cw(c3779.98,3796.79) 3839.2,3796.79 cw(c3898.41,3796.79) H5.14@3856.54,3838.66 ; H5.14@3828.92,3845.73 cw(c3804.12,3820.93) 3839.2,3820.93 cw(c3874.27,3820.93) H5.14@3849.47,3845.73 ; v1@3832.83,3668.64 cw(c3817.47,3653.27) 3839.2,3653.27 cw(c3860.93,3653.27) v1@3845.56,3668.64 ; v1@3832.83,3681.36 ccw(c3817.47,3696.73) 3839.2,3696.73 ccw(c3860.93,3696.73) v1@3845.56,3681.36 ; H5.14@3839.2,3856 3839.2,3581.06 U2.46@4489.43,2930.82
  Bottom Layer w10: P9.2@2325,2830 P9.2@2335,2830 2430,2830 ; 2433.68,2831.32 3277.35,3675 v1(3839.2,3675)
OCDSDA: H5.15 P9.3 U2.47 | length 3239.8
  Top Layer w10: H5.15@3739.2,3956 3785,3910.2 3785,3612.63 U2.47@4478.12,2919.51 ; v1@3778.64,3633.64 cw(c3763.27,3618.27) 3785,3618.27 cw(c3806.73,3618.27) v1@3791.36,3633.64 ; v1@3778.64,3646.36 ccw(c3763.27,3661.73) 3785,3661.73 ccw(c3806.73,3661.73) v1@3791.36,3646.36
  Bottom Layer w10: P9.3@2325,2730 2380,2730 ; 2385,2725 3300,3640 ; 3305,3640 v1(3785,3640)
PB2: H6.12 RST_N.1 U2.60 | length 3190.2
  Top Layer w10: H6.12@4225.03,1713.34 ccw(c4183.16,1755.21) 4242.38,1755.21 ccw(c4301.59,1755.21) H6.12@4259.72,1713.34 ; H6.12@4232.1,1706.27 ccw(c4207.3,1731.07) 4242.38,1731.07 ccw(c4277.45,1731.07) H6.12@4252.65,1706.27 ; v1@4233.64,2133.64 cw(c4212.54,2112.54) 4242.38,2112.54 ; v1@4233.64,2146.36 ccw(c4212.54,2167.46) 4242.38,2167.46 ; H6.12@4242.38,1696 4242.38,2352.84 U2.60@4591.26,2701.72 ; 4242.38,2124.01 cw(c4255.99,2124.01) v1@4246.36,2133.64 ; 4242.38,2155.99 ccw(c4255.99,2155.99) v1@4246.36,2146.36
  Bottom Layer w10: v1(4240,2140) 4330,2050 5530.25,2050 5668.43,2188.17 v1(5934.97,2188.17) ; v1@5928.61,2181.81 ccw(c5913.25,2166.44) 5913.25,2188.17 ccw(c5913.25,2209.9) v1@5928.61,2194.53
PB6: H6.1 U2.49 WAKE.1 | length 3953.1
  Top Layer w10: H6.1@3742.38,1596 3685,1653.37 v1(3685,1940) 3685,2044.36 U2.49@4466.81,2826.17
  Bottom Layer w10: v1(3685,1940) 3720,1905 5667.39,1905 v1(5934.97,1637.41)
PB7: H5.16 PDN.1 U2.48 | length 3773
  Top Layer w10: H5.16@3739.2,3856 3739.2,3635.8 U2.48@4466.81,2908.19 4486.64,2888.36 ; U2.48@4480.62,2892.43 ccw(c4486.64,2894.85) 4486.64,2888.36 ; U2.48@4480.95,2891.93 ccw(c4489.58,2900.56) 4489.58,2888.36 ; v1@4496.01,2879.5 ccw(c4486.64,2878.97) 4486.64,2888.36 ; v1(4505,2880) 4496.64,2888.36 4486.64,2888.36
  Bottom Layer w10: v1@4505,2871 cw(c4505,2849.27) 4520.36,2864.64 cw(c4535.73,2880) v1@4514,2880 ; v1(4505,2880) 4525,2860 4525,2279.84 4704.84,2100 5535,2100 5810.96,2375.96 v1(6136.05,2375.96)
PLCD: C8.1 H3.15 U2.15 | length 1883.9
  Top Layer w10: 4857.09,2837.63 ccw(c4869.3,2837.63) U2.15@4860.66,2829 ; C8.1@5016.16,2861.16 ccw(c4994.82,2839.82) 4994.82,2870 ccw(c4994.82,2900.18) C8.1@5016.16,2878.84 ; C8.1@5025,2870 4875,2870 4857.09,2852.09 4857.09,2834.7 U2.15@4876.93,2814.86 5691,2000.78 H3.15@5691,1694 ; H3.15@5673.66,1711.34 ccw(c5631.79,1753.21) 5691,1753.21 ccw(c5750.21,1753.21) H3.15@5708.34,1711.34 ; H3.15@5680.73,1704.27 ccw(c5655.93,1729.07) 5691,1729.07 ccw(c5726.07,1729.07) H3.15@5701.27,1704.27
SCK: H6.6 P7.2 SCK.1 U2.54 | length 6420
  Top Layer w10: H6.6@3925.03,1713.34 ccw(c3890.83,1747.54) 3939.2,1747.54 ; v1@3932.83,2048.64 cw(c3917.47,2033.27) 3939.2,2033.27 cw(c3960.93,2033.27) v1@3945.56,2048.64 ; v1@3932.83,2061.36 ccw(c3909.8,2084.4) 3942.38,2084.4 ; 3939.2,1738.74 ccw(c3985.12,1738.74) H6.6@3952.65,1706.27 ; 3939.2,1762.88 ccw(c4009.26,1762.88) H6.6@3959.72,1713.34 ; v1(3939.2,2055) 3939.2,1699.17 H6.6@3942.38,1696 ; v1@3942.38,2055 3942.38,2188.6 U2.54@4523.37,2769.6 4578.77,2825 v1(4580,2825) ; 3942.38,2069.05 ccw(c3953.25,2069.05) v1@3945.56,2061.36 ; 4562.54,2808.77 cw(c4580,2791.31) v1@4580,2816 ; 4565.5,2811.73 ccw(c4552.24,2825) v1@4571,2825
  Bottom Layer w10: v1(3939.2,2055) 3992.45,2001.75 v1(5934.97,2001.75) ; v1(4580,2825) 4605.15,2825 4630.15,2800 4935,2800 5910,3775 6843.66,3775 P7.2@6857.36,3788.7 ; v1@4586.36,2818.64 cw(c4601.73,2803.27) 4601.73,2825 cw(c4601.73,2846.73) v1@4586.36,2831.36 ; v1@5928.61,1995.39 ccw(c5913.25,1980.02) 5913.25,2001.75 ccw(c5913.25,2023.48) v1@5928.61,2008.12 ; P7.2@6862.36,3773.7 P7.2@6872.36,3773.7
